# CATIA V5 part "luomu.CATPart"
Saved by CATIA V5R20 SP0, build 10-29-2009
Part number: 螺母
Material "Steel": density 7860 kg/m3, Young's modulus 2e+11 Pa, Poisson ratio 0.266, thermal expansion 1.17e-05 1/K
Bounding box of the stored display mesh (mm): x -30 to 30, y -25.981 to 25.981, z -5 to 5
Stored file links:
  F:\CATIA\XLW\luomu.CATPart
  D:\CATIA\intel_a\reffiles\standard\MetricThickPitch.txt
  D:\CATIA\intel_a\reffiles\standard\MetricThinPitch.txt
  D:\CATIA\intel_a\startup\materials\Catalog.CATMaterial
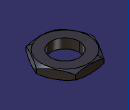
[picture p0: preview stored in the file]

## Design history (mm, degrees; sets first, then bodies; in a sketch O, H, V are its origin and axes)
Body1 (main body), material "Steel"
  Sketch1 on xy-plane, origin (0, 0, 0), H (1, 0, 0), V (0, 1, 0)
    circle A1 centre (0, 0) radius 15
    point P1 (15, 25.9808)
    point P2 (-15, 25.9808)
    point P3 (-30, 0)
    point P4 (-15, -25.9808)
    point P5 (15, -25.9808)
    point P6 (30, 0)
    point P7 (0, 25.9808)
    line L1 (15, 25.9808) -> (-15, 25.9808)
    line L2 (-15, 25.9808) -> (-30, 0)
    line L3 (-30, 0) -> (-15, -25.9808)
    line L4 (-15, -25.9808) -> (15, -25.9808)
    line L5 (15, -25.9808) -> (30, 0)
    line L6 (30, 0) -> (15, 25.9808)
    construction line L7 (0, 0) -> (0, 25.9808)
    construction circle A2 centre (0, 0) radius 30
    construction arc A3 centre (15, -25.9808) radius 30 from (-15, -25.9808) to (30, 0) cw
    construction arc A4 centre (-15, 25.9808) radius 30 from (-30, 0) to (15, 25.9808) ccw
    radius A1 = 15
    radius A3 = 30
    vertical: L7 V
    coincidence: A2 P1, A2 P2, A2 P3, A2 P4, A2 P5, A2 P6, A3 O, A4 O
    midpoint: P7 L1
    parallelism: L1 L4
  Pad1: profile Sketch1, direction (0, 0, 1), length 5, mirrored extent
  Sketch2 on yz-plane, origin (0, 0, 0), H (0, 1, 0), V (0, 0, 1)
  Sketch3 on yz-plane, origin (0, 0, 0), H (0, 1, 0), V (0, 0, 1)
    line L1 (-25.2537, 5) -> (-33.914, 5)
    line L2 (-33.914, 5) -> (-33.914, 0)
    point P3 (-33.914, 0)
    line L3 (-33.914, 0) -> (-25.2537, 5)
    reference projected line E1 (-25.9808, 5) -> (0, 5) from edge [face of Pad1 from Sketch1.L5 | end face of Pad1]
    angle L1 L3 = 30
    horizontal: L1 H
    coincidence: P3 H, L1 E1
    vertical: L2 V
  Groove1: profile Sketch3, axis Sketch3.V, angle 360
  Mirror1: of Groove1, about xy-plane
  Thread1: diameter 33, depth 20, pitch 1, on face of Pad1 from Sketch1.A1, from end face of Pad1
